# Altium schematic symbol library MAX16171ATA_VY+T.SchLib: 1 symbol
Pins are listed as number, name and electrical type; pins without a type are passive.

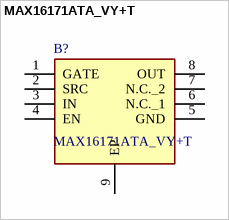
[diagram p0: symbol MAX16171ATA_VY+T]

## MAX16171ATA_VY+T
designator B?
Ideal Diode Controller with Reverse-Current Protection, 8 TDFN-CU; Manufacturer_Name: Analog Devices; Manufacturer_Part_Number: MAX16171ATA/VY+T; Geometry.Height: 0.8mm
footprint SON50P300X200X80-9N
pins: 1 GATE, 2 SRC, 3 IN, 4 EN, 5 GND, 6 N.C._1, 7 N.C._2, 8 OUT, 9 EP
